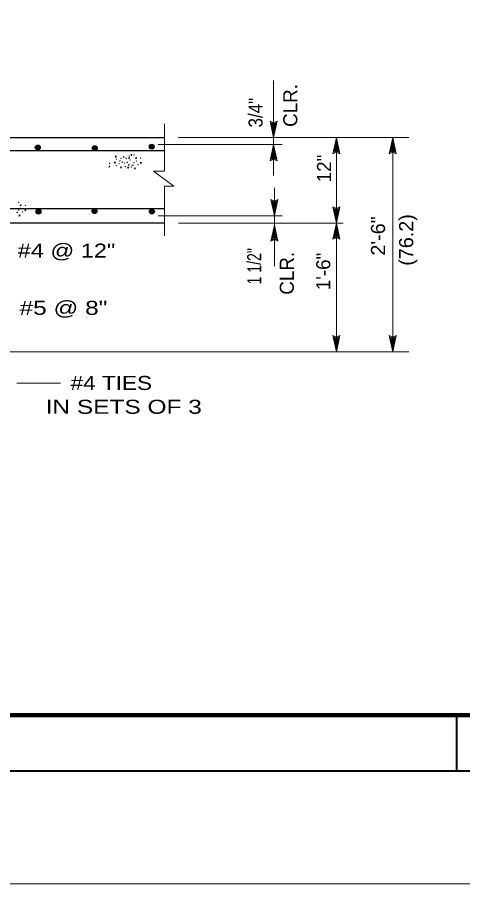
# Model space of a CAD drawing. Extents: x -28.1 to 13.9, y -16.1 to 13.9.
# Drawn here: x -15.05 to -11.09, y -16.13 to -8.42 of the extents above; entities that cross this region are included whole.
import ezdxf
from ezdxf.enums import TextEntityAlignment as Align

# ---------------------------------------------------------------- set-up
doc = ezdxf.new("R2010")
doc.units = 0
doc.header["$LTSCALE"] = 0.05
doc.layers.add('1', color=7, linetype='Continuous', lineweight=13)
doc.layers.add('2', color=7, linetype='Continuous', lineweight=13)

msp = doc.modelspace()

# ---------------------------------------------------------------- linework, layer by layer
at = {"layer": '1'}
for p, q in [((-13.73804, -9.79031), (-13.73804, -9.36931)), ((-12.76804, -9.49031), (-12.79904, -9.34631)), ((-12.76804, -9.45331), (-12.78804, -9.35931)), ((-12.78804, -9.35931), (-12.76804, -9.36831)), ((-12.76804, -9.41731), (-12.77804, -9.37231)), ((-12.77804, -9.37231), (-12.76804, -9.37631)), ((-12.76804, -9.49031), (-12.73704, -9.34631)), ((-12.76804, -9.45331), (-12.74804, -9.35931)), ((-12.76804, -9.36831), (-12.74804, -9.35931)), ((-12.76804, -9.41731), (-12.75904, -9.37231)), ((-12.76804, -9.37631), (-12.75904, -9.37231)), ((-13.79404, -9.55431), (-12.69104, -9.55431)), ((-13.61404, -9.49131), (-11.56504, -9.49131)), ((-12.76804, -9.55331), (-12.79904, -9.69731)), ((-12.76804, -9.55331), (-12.73704, -9.69731)), ((-12.20904, -9.49131), (-12.24004, -9.63531)), ((-12.20904, -9.52831), (-12.22904, -9.62231)), ((-12.20904, -9.49131), (-12.17804, -9.63531)), ((-12.20904, -9.52831), (-12.18904, -9.62231)), ((-11.70804, -9.49131), (-11.73904, -9.63531)), ((-11.70804, -9.52831), (-11.72804, -9.62231)), ((-11.70804, -9.52831), (-11.68804, -9.62231)), ((-12.76804, -9.59031), (-12.78804, -9.68431)), ((-12.76804, -9.62631), (-12.77704, -9.67131)), ((-12.76804, -9.59031), (-12.74804, -9.68431)), ((-12.76804, -9.62631), (-12.75804, -9.67131)), ((-12.20904, -9.61331), (-12.22904, -9.62231)), ((-12.20904, -9.56431), (-12.21804, -9.60931)), ((-12.20904, -9.60531), (-12.21804, -9.60931)), ((-12.20904, -9.56431), (-12.19904, -9.60931)), ((-12.19904, -9.60931), (-12.20904, -9.60531)), ((-12.18904, -9.62231), (-12.20904, -9.61331)), ((-11.70804, -9.61331), (-11.72804, -9.62231)), ((-11.70804, -9.56431), (-11.71704, -9.60931)), ((-11.70804, -9.60531), (-11.71704, -9.60931)), ((-11.70804, -9.56431), (-11.69804, -9.60931)), ((-11.69804, -9.60931), (-11.70804, -9.60531)), ((-11.68804, -9.62231), (-11.70804, -9.61331)), ((-12.76804, -9.67531), (-12.78804, -9.68431)), ((-12.76804, -9.66731), (-12.77704, -9.67131)), ((-12.75804, -9.67131), (-12.76804, -9.66731)), ((-12.74804, -9.68431), (-12.76804, -9.67531)), ((-13.73804, -9.79031), (-13.83504, -9.79031)), ((-13.65404, -9.92431), (-13.83504, -9.79031)), ((-13.65404, -9.92431), (-13.73804, -9.92431)), ((-13.73804, -10.36631), (-13.73804, -9.92431)), ((-12.76104, -10.18731), (-12.79204, -10.04331)), ((-12.76104, -10.15031), (-12.78104, -10.05631)), ((-12.78104, -10.05631), (-12.76104, -10.06531)), ((-12.76104, -10.11431), (-12.77104, -10.06931)), ((-12.77104, -10.06931), (-12.76104, -10.07331)), ((-12.76104, -10.18731), (-12.73004, -10.04331)), ((-12.76104, -10.15031), (-12.74104, -10.05631)), ((-12.76104, -10.06531), (-12.74104, -10.05631)), ((-12.76104, -10.11431), (-12.75204, -10.06931)), ((-12.76104, -10.07331), (-12.75204, -10.06931)), ((-12.20904, -10.25231), (-12.24004, -10.10831)), ((-12.20904, -10.21531), (-12.22904, -10.12131)), ((-12.22904, -10.12131), (-12.20904, -10.13031)), ((-12.20904, -10.17931), (-12.21904, -10.13431)), ((-12.21904, -10.13431), (-12.20904, -10.13831)), ((-12.20904, -10.25231), (-12.17804, -10.10831)), ((-12.20904, -10.21531), (-12.18904, -10.12131)), ((-12.20904, -10.13031), (-12.18904, -10.12131)), ((-12.20904, -10.17931), (-12.20004, -10.13431)), ((-12.20904, -10.13831), (-12.20004, -10.13431)), ((-13.79404, -10.18731), (-12.69104, -10.18731)), ((-13.61404, -10.25231), (-12.14904, -10.25231)), ((-12.76104, -10.26931), (-12.79204, -10.41331)), ((-12.76104, -10.30631), (-12.78104, -10.40031)), ((-12.76104, -10.26931), (-12.73004, -10.41331)), ((-12.76104, -10.30631), (-12.74104, -10.40031)), ((-12.20904, -10.25231), (-12.24004, -10.39631)), ((-12.20904, -10.28931), (-12.22904, -10.38331)), ((-12.20904, -10.25231), (-12.17804, -10.39631)), ((-12.20904, -10.28931), (-12.18904, -10.38331)), ((-12.76104, -10.39131), (-12.78104, -10.40031)), ((-12.76104, -10.34231), (-12.77004, -10.38731)), ((-12.76104, -10.38331), (-12.77004, -10.38731)), ((-12.76104, -10.34231), (-12.75104, -10.38731)), ((-12.75104, -10.38731), (-12.76104, -10.38331)), ((-12.74104, -10.40031), (-12.76104, -10.39131)), ((-12.20904, -10.37431), (-12.22904, -10.38331)), ((-12.20904, -10.32531), (-12.21804, -10.37031)), ((-12.20904, -10.36631), (-12.21804, -10.37031)), ((-12.20904, -10.32531), (-12.19904, -10.37031)), ((-12.19904, -10.37031), (-12.20904, -10.36631)), ((-12.18904, -10.38331), (-12.20904, -10.37431)), ((-12.20904, -11.39631), (-12.24004, -11.25231)), ((-12.20904, -11.35931), (-12.22904, -11.26531)), ((-12.22904, -11.26531), (-12.20904, -11.27431)), ((-12.20904, -11.32331), (-12.21904, -11.27831)), ((-12.21904, -11.27831), (-12.20904, -11.28231)), ((-12.20904, -11.39631), (-12.17804, -11.25231)), ((-12.20904, -11.35931), (-12.18904, -11.26531)), ((-12.20904, -11.27431), (-12.18904, -11.26531)), ((-12.20904, -11.32331), (-12.20004, -11.27831)), ((-12.20904, -11.28231), (-12.20004, -11.27831)), ((-11.70804, -11.39631), (-11.73904, -11.25231)), ((-11.70804, -11.35931), (-11.72804, -11.26531)), ((-11.72804, -11.26531), (-11.70804, -11.27431)), ((-11.70804, -11.32331), (-11.71804, -11.27831)), ((-11.71804, -11.27831), (-11.70804, -11.28231)), ((-11.70804, -11.39631), (-11.67704, -11.25231)), ((-11.70804, -11.35931), (-11.68804, -11.26531)), ((-11.70804, -11.27431), (-11.68804, -11.26531)), ((-11.70804, -11.32331), (-11.69904, -11.27831)), ((-11.70804, -11.28231), (-11.69904, -11.27831)), ((-15.47804, -11.39631), (-11.56504, -11.39631)), ((-15.05104, -11.67531), (-14.66204, -11.67531)), ((13.85696, -16.12731), (-28.14304, -16.12731))]:
    msp.add_line(p, q, dxfattribs=at)
at = {"layer": '1', "lineweight": 25}
for p, q in [((-18.82104, -9.49131), (-13.73804, -9.49131)), ((-18.82204, -9.60631), (-13.73904, -9.60631)), ((-16.94504, -10.12331), (-13.73804, -10.12331)), ((-13.73804, -10.25231), (-15.57304, -10.25231))]:
    msp.add_line(p, q, dxfattribs=at)
at = {"layer": '1', "lineweight": 40}
msp.add_line((-11.14304, -14.62731), (-11.14304, -15.12731), dxfattribs=at)
msp.add_lwpolyline([(-27.14304, -15.12731), (-27.14304, 12.87269), (12.85696, 12.87269), (12.85696, -15.12731)], close=True, dxfattribs=at)
at = {"layer": '1', "lineweight": 90}
msp.add_lwpolyline([(-25.64304, 12.37269), (12.35696, 12.37269), (12.35696, -14.62731), (-25.64304, -14.62731)], close=True, dxfattribs=at)
at = {"layer": '1'}
for points in [[(-12.76804, -9.82831), (-12.76804, -9.55331), (-12.76804, -9.49031), (-12.76804, -8.98231)], [(-12.79904, -9.34631), (-12.76804, -9.36031), (-12.73704, -9.34631)], [(-12.20904, -11.39631), (-12.20904, -10.25231), (-12.20904, -9.49131)], [(-11.70804, -11.39631), (-11.70804, -9.49131), (-11.67704, -9.63531)], [(-12.17804, -9.63531), (-12.20904, -9.62131), (-12.24004, -9.63531)], [(-11.67704, -9.63531), (-11.70804, -9.62131), (-11.73904, -9.63531)], [(-12.73704, -9.69731), (-12.76804, -9.68331), (-12.79904, -9.69731)], [(-12.76104, -10.63431), (-12.76104, -10.26931), (-12.76104, -10.18731), (-12.76104, -9.93731)], [(-12.79204, -10.04331), (-12.76104, -10.05731), (-12.73004, -10.04331)], [(-12.24004, -10.10831), (-12.20904, -10.12231), (-12.17804, -10.10831)], [(-12.73004, -10.41331), (-12.76104, -10.39931), (-12.79204, -10.41331)], [(-12.17804, -10.39631), (-12.20904, -10.38231), (-12.24004, -10.39631)], [(-12.24004, -11.25231), (-12.20904, -11.26631), (-12.17804, -11.25231)], [(-11.73904, -11.25231), (-11.70804, -11.26631), (-11.67704, -11.25231)]]:
    msp.add_lwpolyline(points, dxfattribs=at)
at = {"layer": '1', "lineweight": 25}
for centre, radius in [((-13.85199, -9.57223), 0.02168), ((-14.86499, -9.58023), 0.02168), ((-14.86499, -9.58023), 0.01681), ((-14.86499, -9.58023), 0.01233), ((-14.86499, -9.58023), 0.00623), ((-14.35799, -9.58623), 0.02168), ((-14.35799, -9.58623), 0.01681), ((-14.35799, -9.58623), 0.01233), ((-14.35799, -9.58623), 0.00623), ((-13.85199, -9.57223), 0.01681), ((-13.85199, -9.57223), 0.01233), ((-13.85199, -9.57223), 0.00623), ((-14.85899, -10.15023), 0.02168), ((-14.85899, -10.15023), 0.01681), ((-14.85899, -10.15023), 0.01233), ((-14.85899, -10.15023), 0.00623), ((-14.36099, -10.14623), 0.02168), ((-14.36099, -10.14623), 0.01681), ((-14.36099, -10.14623), 0.01233), ((-14.36099, -10.14623), 0.00623), ((-13.84999, -10.14823), 0.02168), ((-13.84999, -10.14823), 0.01681), ((-13.84999, -10.14823), 0.01233), ((-13.84999, -10.14823), 0.00623)]:
    msp.add_circle(centre, radius, dxfattribs=at)
at = {"layer": '2'}
msp.add_line((-14.09804, -9.66331), (-14.10404, -9.65831), dxfattribs=at)
for points in [[(-14.17104, -9.65331), (-14.16604, -9.66331), (-14.17604, -9.66431), (-14.16804, -9.65331)], [(-14.13104, -9.69831), (-14.13604, -9.69631), (-14.13904, -9.70231), (-14.13104, -9.69931)], [(-14.11104, -9.71131), (-14.11404, -9.70731), (-14.11904, -9.71131), (-14.11204, -9.71231)], [(-14.10404, -9.65831), (-14.10604, -9.66531), (-14.09804, -9.66531)], [(-14.05304, -9.66531), (-14.04804, -9.67531), (-14.05904, -9.67631), (-14.05104, -9.66531)], [(-14.03204, -9.65131), (-14.02704, -9.64231), (-14.03804, -9.64231), (-14.03204, -9.65331)], [(-13.99104, -9.66631), (-13.98604, -9.67631), (-13.99604, -9.67731), (-13.98804, -9.66631)], [(-14.22804, -9.74231), (-14.22304, -9.75231), (-14.23304, -9.75331), (-14.22604, -9.74231)], [(-14.17904, -9.71831), (-14.17404, -9.71031), (-14.18504, -9.71031), (-14.17904, -9.72031)], [(-14.12504, -9.74931), (-14.12004, -9.75931), (-14.13004, -9.76031), (-14.12204, -9.74931)], [(-14.06004, -9.76331), (-14.05504, -9.75431), (-14.06604, -9.75431), (-14.06004, -9.76431)], [(-14.01804, -9.73731), (-14.02304, -9.73431), (-14.02704, -9.73731), (-14.01504, -9.73931)], [(-14.00104, -9.75831), (-13.99604, -9.76831), (-14.00604, -9.76931), (-13.99804, -9.75831)], [(-13.94904, -9.72231), (-13.94404, -9.71431), (-13.95504, -9.71431), (-13.94904, -9.72431)], [(-15.01704, -10.08631), (-15.01204, -10.09631), (-15.02204, -10.09731), (-15.01404, -10.08631)], [(-15.04404, -10.15731), (-15.04904, -10.15431), (-15.05304, -10.15731), (-15.04104, -10.15931)], [(-14.97504, -10.14231), (-14.97004, -10.13431), (-14.98104, -10.13431), (-14.97504, -10.14431)], [(-15.02704, -10.17831), (-15.02204, -10.18831), (-15.03204, -10.18931), (-15.02404, -10.17831)]]:
    msp.add_lwpolyline(points, dxfattribs=at)
for points in [[(-14.06604, -9.71631), (-14.07104, -9.70731), (-14.07404, -9.71331)], [(-14.05104, -9.73731), (-14.05604, -9.72931), (-14.05904, -9.73531)]]:
    msp.add_lwpolyline(points, close=True, dxfattribs=at)
for centre in [(-14.16629, -9.68269), (-14.12504, -9.67694), (-14.07879, -9.67594), (-14.05104, -9.65419), (-14.04354, -9.69119), (-14.00829, -9.64744), (-13.98979, -9.69944), (-13.95004, -9.67419), (-14.22454, -9.72044), (-14.16729, -9.73994), (-14.14204, -9.72219), (-14.09404, -9.71644), (-14.08654, -9.75094), (-14.03254, -9.75344), (-14.00904, -9.71469), (-13.97454, -9.73319), (-15.03429, -10.06744), (-14.97604, -10.09419), (-15.03504, -10.13469), (-15.01579, -10.11944), (-15.00054, -10.15319)]:
    msp.add_circle(centre, 0.00162, dxfattribs=at)

# ---------------------------------------------------------------- texts
at = {"layer": '1'}
msp.add_text('CLR.', height=0.125, rotation=90, dxfattribs=at).set_placement((-12.55704, -9.39631))
at = {"layer": '1', "width": 0.9}
msp.add_text('3/4"', height=0.125, rotation=90, dxfattribs=at).set_placement((-12.86604, -9.40131))
at = {"layer": '1'}
for s, p in [('12"', (-12.25704, -9.7663)), ('CLR.', (-12.58804, -10.69841)), ('1\'-6"', (-12.26404, -10.6825))]:
    msp.add_text(s, height=0.125, rotation=90, dxfattribs=at).set_placement(p, align=Align.CENTER)
at = {"layer": '1', "width": 1.05}
for s, p in [('2\'-6"', (-11.77704, -10.36643)), ('(76.2)', (-11.52704, -10.40218))]:
    msp.add_text(s, height=0.125, rotation=90, dxfattribs=at).set_placement(p, align=Align.CENTER)
at = {"layer": '1'}
for s, width, p in [('#4 @ 12"', 1.25, (-15.04304, -10.55931)), ('#5 @ 8"', 1.3, (-15.02704, -11.06831))]:
    msp.add_text(s, height=0.125, dxfattribs=dict(at, width=width)).set_placement(p)
at = {"layer": '1', "width": 0.75}
msp.add_text('1 1/2"', height=0.125, rotation=90, dxfattribs=at).set_placement((-12.87804, -10.47458), align=Align.RIGHT)
at = {"layer": '1'}
for s, width, p in [('#4 TIES', 1.2, (-14.21096, -11.73631)), ('IN SETS OF 3', 1.3, (-14.10053, -11.94831))]:
    msp.add_text(s, height=0.125, dxfattribs=dict(at, width=width)).set_placement(p, align=Align.CENTER)

doc.saveas('drawing.dxf')
